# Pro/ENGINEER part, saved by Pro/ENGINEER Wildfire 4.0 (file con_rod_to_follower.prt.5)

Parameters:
  METRIC = "NO"

Other parameters: PITCH, DRILL_POINT_ANGLE, DRILL_DEPTH, DRILL_DIAMETER, THREAD_DIAMETER, THREADS_PER_INCH, THREAD_DEPTH, THREAD_LENGTH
